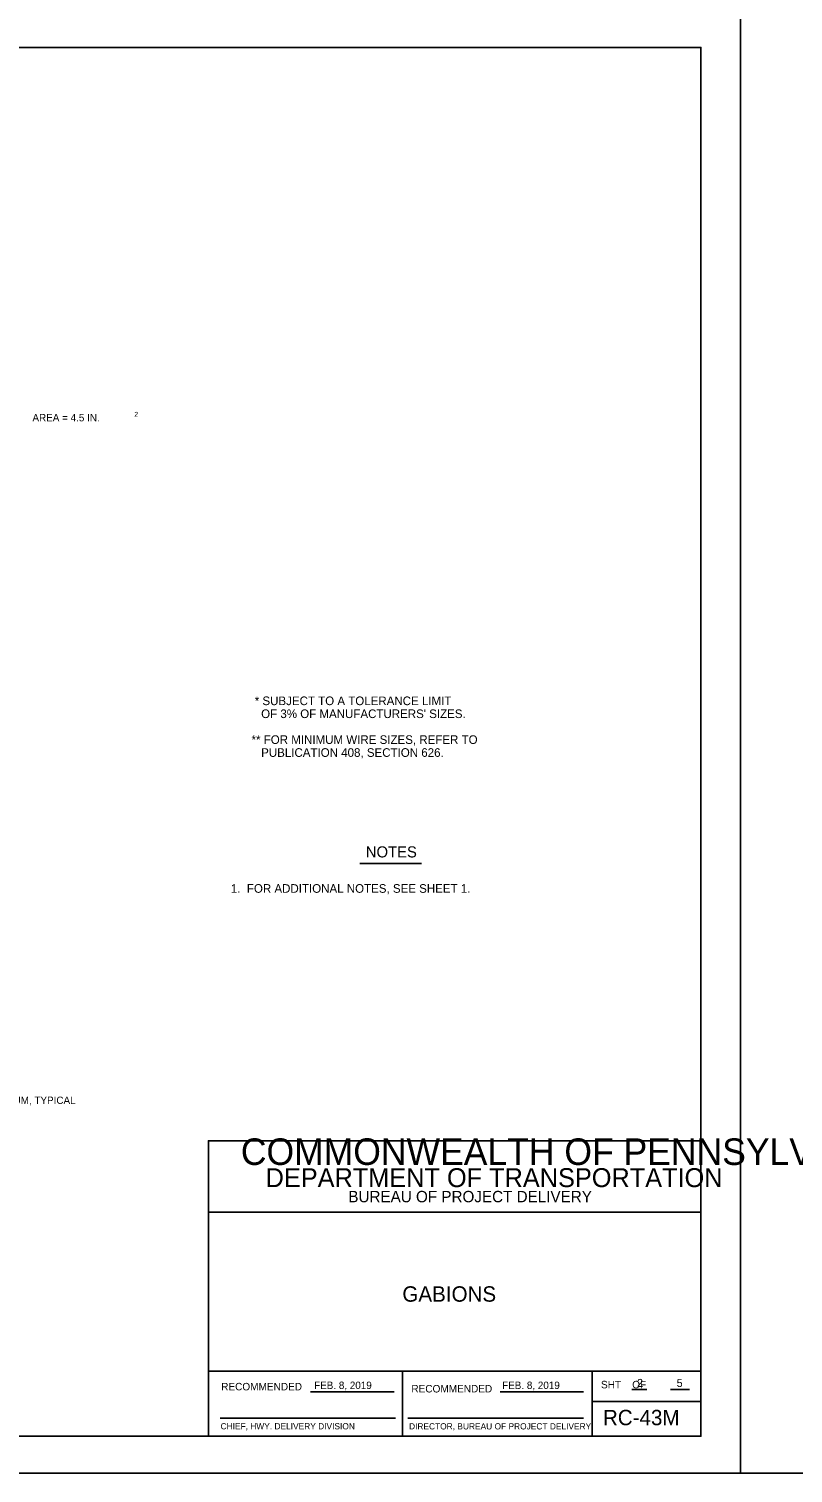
# Model space of a CAD drawing. Extents: x 3 to 3592, y -602 to 1171.
# Drawn here: x 555 to 865, y -17 to 569 of the extents above; entities that cross this region are included whole.
import ezdxf

# ---------------------------------------------------------------- set-up
doc = ezdxf.new("R2010")
doc.units = 0
for name, color, linetype in [('1', 7, 'Continuous'), ('3', 7, 'Continuous'), ('PLT-BNDY', 7, 'Continuous')]:
    doc.layers.add(name, color=color, linetype=linetype)

msp = doc.modelspace()

# ---------------------------------------------------------------- linework, layer by layer
at = {"layer": '1'}
for p, q in [((668.97, 15.82), (702.86, 15.82)), ((745.97, 15.82), (779.84, 15.82)), ((799.37, 16.81), (805.51, 16.81)), ((815.18, 16.81), (822.83, 16.81)), ((632.27, 5.16), (703.52, 5.16)), ((708.44, 5.16), (779.78, 5.16))]:
    msp.add_line(p, q, dxfattribs=at)
msp.add_lwpolyline([(827.51, -2.17), (827.51, 561.83), (41.51, 561.83), (41.51, -2.17), (827.51, -2.17), (827.51, 24.19), (627.51, 24.19), (627.51, 88.87), (827.51, 88.87), (827.51, 117.83), (627.51, 117.83), (627.51, -2.17), (706.31, -2.17), (706.31, 24.19), (706.31, -2.17), (783.31, -2.17), (783.31, 24.19), (783.31, 11.88), (827.51, 11.88)], dxfattribs=at)
at = {"layer": '3'}
msp.add_line((688.97, 230.41), (713.96, 230.41), dxfattribs=at)
at = {"layer": 'PLT-BNDY'}
for points in [[(2.51, 576.83), (843.51, 576.83), (843.51, -17.17), (2.51, -17.17)], [(843.51, 576.83), (1684.51, 576.83), (1684.51, -17.17), (843.51, -17.17)]]:
    msp.add_lwpolyline(points, close=True, dxfattribs=at)

# ---------------------------------------------------------------- texts
at = {"layer": '1'}
for s, height, p in [('COMMONWEALTH OF PENNSYLVANIA', 10.7834, (640.66, 107.98)), ('DEPARTMENT OF TRANSPORTATION', 7.6843, (650.72, 98.98)), ('BUREAU OF PROJECT DELIVERY', 4.6221, (684.31, 92.82)), ('GABIONS', 6.25, (706.25, 52.45)), ('RECOMMENDED', 3.048, (632.67, 16.43)), ('FEB. 8, 2019', 3, (670.42, 17)), ('RECOMMENDED', 3.048, (709.91, 15.59)), ('FEB. 8, 2019', 3, (746.77, 17)), ('SHT    OF', 3.048, (786.91, 17.26)), ('2', 3.25, (801.57, 17.83)), ('5', 3.25, (817.65, 17.83)), ('APPROVED', 0.0192, (670.53, 15.77)), ('RC-43M', 6.25, (787.7, 2.28)), ('CHIEF, HWY. DELIVERY DIVISION', 2.54, (632.42, 0.6)), ('DIRECTOR, BUREAU OF PROJECT DELIVERY', 2.54, (708.96, 0.57))]:
    msp.add_text(s, height=height, dxfattribs=at).set_placement(p)
at = {"layer": '3'}
for s, height, p in [('AREA = 4.5 IN.', 3, (556.04, 409.95)), (' * SUBJECT TO A TOLERANCE LIMIT', 3.5, (645.01, 294.71)), ("   OF 3% OF MANUFACTURERS' SIZES.", 3.5, (645.01, 289.46)), ('** FOR MINIMUM WIRE SIZES, REFER TO', 3.5, (645.01, 278.96)), ('   PUBLICATION 408, SECTION 626.', 3.5, (645.01, 273.71)), ('NOTES', 4.5, (691.41, 232.86)), ('1.  FOR ADDITIONAL NOTES, SEE SHEET 1.', 3.5, (636.61, 218.51)), ('(**) GAUGE, MINIMUM, TYPICAL', 3, (512.93, 132.73))]:
    msp.add_text(s, height=height, dxfattribs=at).set_placement(p)
msp.add_text('2', height=2, rotation=360, dxfattribs=at).set_placement((597.39, 411.8))

doc.saveas('drawing.dxf')
